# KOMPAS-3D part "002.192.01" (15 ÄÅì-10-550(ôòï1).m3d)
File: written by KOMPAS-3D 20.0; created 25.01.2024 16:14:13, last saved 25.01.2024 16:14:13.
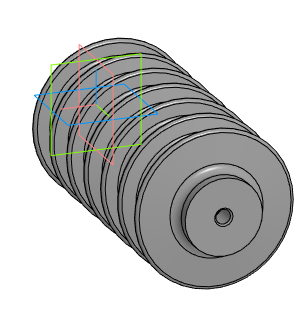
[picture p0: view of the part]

Document properties: Полное имя файла: C:\Users\drmla\OneDrive\Рабочий стол\ОПН\Модели\002.192.01.m3d

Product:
- Part/product: 002.192.01

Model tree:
1. Операция без истории:1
